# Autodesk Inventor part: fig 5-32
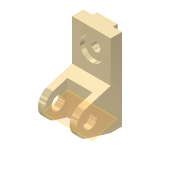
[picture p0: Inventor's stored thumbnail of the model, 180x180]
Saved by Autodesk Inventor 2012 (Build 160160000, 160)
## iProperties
Shininess: 65.0
Angle Display Precision: 2
Document Length Units: 11269
Document Angle Units: 11279
Document Time Units: 11290
Document Mass Units: 11283
Document Length Units Precision: 3
Document Angle Units Precision: 2
Created: 2001-11
Part Number: fig 5-32
Document SubType Name: Modeling
Designer: Renu Muthoo
Density: 1 g/cm^3
Material: Default
Density: 0.0
Volumn: 0.0
Area: 0.0
PropertySet Name: Model Information
Control State: 0
Master: False
Checked Out: False
Author: Renu Muthoo
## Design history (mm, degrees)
node "Sketch1"
sketch "Sketch2"
  geometry: L1 (33.257, 104.664)-(33.257, -75.336); L2 (33.257, -75.336)-(8.257, -75.336); L3 (8.257, -75.336)-(-45.451, -59.045); L4 (-45.451, -1.628)-(8.257, 14.664); L5 (8.257, 14.664)-(8.257, 104.664); L6 (8.257, 104.664)-(33.257, 104.664); C1 r 15 at (-36.743, -30.336); A1 r 30 centre (-36.743, -30.336) between (-45.451, -1.628) and (-45.451, -59.045)
  constraints: 12 end point, 2 centre point, 2 equal length, 2 parallel, 2 point on circle, 2 tangent, 1 coincident, 1 perpendicular, 1 vertical
  dimensions: "d0" = 180 distance of L1.start L1.end; "d1" = 30 radius of A1; "d2" = 25 distance of L5.end L1.start; "d3" = 45 distance from line of L2 A1.centre; "d4" = 70 distance from line of L1 A1.centre; "d5" = 30 diameter of C1
extrude "Extrusion1" new body sketch "Sketch2" distance "d6" = 85; taper "d7" = 0 deg
workplane "Work Plane1"
sketch "Sketch3"
  geometry: L1 (15, 62.364)-(70, 62.364); L2 (70, 62.364)-(70, -52.386); L3 (70, -52.386)-(15, -52.386); L4 (15, -52.386)-(15, 62.364); L5 (0, -45)-(0, -28.708) reference
  constraints: 8 end point, 2 parallel, 1 horizontal, 1 perpendicular
  dimensions: "d8" = 55 distance of L1.start L1.end; "d9" = 15 distance between parallel lines of L5 L4
extrude "Extrusion2" cut sketch "Sketch3" distance "d10" = 50; taper "d11" = 0 deg
sketch "Sketch4"
  geometry: L1 (0, 25)-(85, 25) reference; L2 (0, 0)-(0, 25) reference; L3 (20, 25)-(65, 25); L4 (65, 25)-(65, 35); L5 (65, 35)-(20, 35); L6 (20, 35)-(20, 25)
  constraints: 8 end point, 2 parallel, 1 horizontal, 1 perpendicular, 1 point on line
  dimensions: "d12" = 45 distance of L4.end L5.end; "d13" = 10 distance of L3.end L4.end; "d14" = 20 distance between parallel lines of L2 L6
extrude "Extrusion3" join sketch "Sketch4" stored distance "d15" = 50; taper "d16" = 0 deg
sketch "Sketch5"
  geometry: L1 (85, 0)-(85, 90) reference; L2 (0, 90)-(85, 90) reference; 1 further point
  dimensions: "d17" = 42 distance from line of L2 point (42.5, 48); "d18" = 42.5 distance from line of L1 point (42.5, 48)
hole "Hole1" sketch "Sketch5" at (42.5, 48) diameter "d19" = 20; stored, may be unused: countersink angle "d23" = 82 deg, drill point angle "d25" = 118 deg; dims "d20" = 6, "d21" = 50, "d22" = 10, "d24" = 8
workplane "Work Plane6"
body "Solid1"
